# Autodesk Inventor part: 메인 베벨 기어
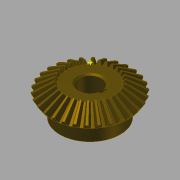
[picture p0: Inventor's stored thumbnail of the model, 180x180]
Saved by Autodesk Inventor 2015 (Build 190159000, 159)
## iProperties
Created: 2014-10
Part Number: 메인 베벨 기어
Material: 강철, 탄소
Document SubType Name: Modeling
Designer: KYOUNG IL JANG
Categories: <?xml version="1.0" encoding="UTF-16"?> <MemberInstance><Categories><FamilyTemplate><FamilyTemplateParameter ValueType="xs:double" Id="1" ObjectReferenceKey="da
Mass: 269.926 g
Surface Area: 108.837 cm^2
Volume: 34.2981 cm^3
Density: 7.87 g/cm^3
Appearance: 얼룩무늬
CustomPartVersion: 1
d48: 0.000 mm
d49: 0.000 mm
d50: 90.00 deg
d52: 0.000 mm
d53: 0.000 mm
d54: 0.00 deg
Author: SeoGD™ [www.esajin.kr]
Revision Number: 1
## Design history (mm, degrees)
node "맨 위 점"
node "메쉬 평면2"
sketch "톱니 본체 스케치"
  geometry: L1 (0, 0)-(28.669, -21.997); L2 (28.669, -21.997)-(31.109, -18.336); L3 (31.109, -18.336)-(0, 0); L4 (30, -20)-(0, 0); L5 (17.219, -13.212)-(18.685, -11.013); L6 (28.669, -21.997)-(17.219, -13.212); L7 (31.109, -18.336)-(18.685, -11.013); L8 (0, -39.387)-(0, 6.564) reference; L9 (0, -20)-(31.109, -20)
  constraints: 16 end point, 4 point on line, 3 perpendicular, 2 collinear, 1 horizontal alignment, 1 vertical alignment
  dimensions: "d0" = 60 diameter of L4.start L8 (= da_de); "d1" = 57.33744 diameter of L1.end L8 (= da_dfe); "d2" = 62.2188 diameter of L2.end L8 (= da_dae); "d3" = 14.4 distance between parallel lines of L2 L5 (= da_b); "d4" = 18.3359 vertical distance of L2.end L1.start (= da_ve)
revolve "톱니 본체" sketch "톱니 본체 스케치" stored, may be unused: angle "d5" = 90 deg
node "시작점"
node "톱니 평면"
sketch "시작 스케치"
  geometry: L1 (0, -23.505)-(0, 10.645) reference; L2 (-0.709, -2.928)-(0.709, -2.928); A1 r 19.188 centre (-19.457, -7.014) between (-0.709, -2.928) and (-3.232, 3.229); A2 r 19.188 centre (19.457, -7.014) between (3.232, 3.229) and (0.709, -2.928); A3 r 57.403 centre (0, -54.083) between (3.232, 3.229) and (-3.232, 3.229); 1 further point
  constraints: 6 point on circle, 3 centre point, 3 symmetric about line, 2 end point, 1 coincident, 1 perpendicular, 1 other
  dimensions: "d7" = 19.18795 radius of A1 (= fd_rr); "d8" = 19.45712 horizontal distance of point (0, -54.083) A1.centre (= fd_x); "d9" = 47.06905 vertical distance of point (0, -54.083) A1.centre (= fd_y); "d57" = 57.40327 radius of A3 (= 0.5 x fd_dva + 0.3 x da_he); "d58" = 51.15527 distance from line of A3.centre L2 (= 0.5 x fd_dva - 1.12 x da_he)
node "끝점"
  node "끝 평면"
sketch "3D 스케치 오른쪽"
  node "Helical Curve Right" dims "d65" = 229.90621 (computed from da_dm, da_delta, da_beta), "d66" = 31.5, "d67" = 60 (= da_de), "d68" = -9.82794 (= -da_delta), "d69" = 8.10972 (computed from fd_loft, da_delta)
node "끝 평면 오른쪽"
sketch "끝 스케치 오른쪽"
  geometry: L1 (0, -41.54)-(0, 13.178) reference; L2 (-0.422, -1.69)-(0.422, -1.69); A1 r 11.427 centre (-11.587, -4.123) between (-0.422, -1.69) and (-1.925, 1.977); A2 r 11.427 centre (11.587, -4.123) between (1.925, 1.977) and (0.422, -1.69); A3 r 34.184 centre (0, -32.153) between (1.925, 1.977) and (-1.925, 1.977); 1 further point
  constraints: 6 point on circle, 3 centre point, 3 symmetric about line, 2 end point, 1 coincident, 1 perpendicular, 1 other
  dimensions: "d70" = 11.58699 horizontal distance of A3.centre A1.centre (computed from fd_x, fd_ratio); "d71" = 28.03028 vertical distance of point (0, -32.153) A1.centre (computed from fd_y, fd_ratio); "d72" = 11.4267 radius of A1 (computed from fd_rr, fd_ratio); "d73" = 30.46369 distance from line of point (0, -32.153) L2 (computed from d58, fd_ratio); "d74" = 34.18446 radius of A3 (computed from d57, fd_ratio)
feature "로프트 오른쪽" sketch "끝 스케치 오른쪽" dims "d75" = 0, "d77" = 0, "d79" = 0, "d80" = 90 deg, "d85" = 20, "d92" = 90 deg, "d93" = 90 deg, "da_teethtype" = 0 [user parameter]
sketch "3D 스케치 왼쪽"
  node "Helical Curve Left" dims "d26" = 229.90621 (computed from da_dm, da_delta, da_beta), "d27" = 8.10972 (computed from fd_loft, da_delta), "d28" = 60 (= da_de), "d29" = -9.82794 (= -da_delta)
node "끝 평면 왼쪽"
sketch "끝 스케치 왼쪽" dims "d56" = 10.3728 (derived)
  geometry: L1 (0, -43.753)-(0, 15.405) reference; L2 (-0.422, -1.678)-(0.422, -1.678); A1 r 11.427 centre (-11.587, -4.111) between (-0.422, -1.678) and (-1.925, 1.988); A2 r 11.427 centre (11.587, -4.111) between (1.925, 1.988) and (0.422, -1.678); A3 r 34.184 centre (0, -32.142) between (1.925, 1.988) and (-1.925, 1.988); 2 further points; 1 other entity
  constraints: 6 point on circle, 3 centre point, 3 symmetric about line, 2 end point, 1 coincident, 2 other
  dimensions: "d30" = 11.4267 radius of A1 (computed from fd_rr, fd_ratio); "d31" = 11.58699 horizontal distance of point (0, -32.142) A1.centre (computed from fd_x, fd_ratio); "d32" = 28.03028 vertical distance of A1.centre point (0, -32.142) (computed from fd_y, fd_ratio); "d61" = 34.18446 radius of A3 (computed from d57, fd_ratio); "d62" = 30.46369 distance from line of point (0, -32.142) L2 (computed from d58, fd_ratio)
feature "로프트 왼쪽" sketch "끝 스케치 왼쪽" dims "d35" = 0, "d37" = 0, "d39" = 0, "d40" = 90 deg, "d84" = 10, "d90" = 90 deg, "d91" = 90 deg, "da_teethtype" = 0 [user parameter]
sketch "본체 스케치"
  geometry: L1 (0, -35.038)-(0, -19.531) reference; L2 (28.669, -21.997)-(17.219, -13.212) reference; L3 (17.219, -13.212)-(0, -13.212); L4 (28.669, -21.997)-(0, -21.997)
  constraints: 4 end point, 2 perpendicular, 2 point on line
revolve "본체 고정" sketch "본체 스케치" stored, may be unused: angle "d46" = 90 deg
feature "피치 지름" dims angle "d47" = 90 deg
sketch "스케치8"
  geometry: C1 r 22.5 at (0, 0); 1 further point
  constraints: 1 centre point, 1 coincident
  dimensions: "d94" = 45 diameter of C1
extrude "돌출1" join sketch "스케치8" distance "d95" = 13; taper "d96" = 0 deg
sketch "스케치9"
  geometry: 1 further point
hole "구멍1" sketch "스케치9" at (0, 0) diameter "d97" = 17; stored, may be unused: countersink angle "d101" = 90 deg, drill point angle "d103" = 118 deg; dims "d98" = 6, "d99" = 4, "d100" = 2, "d102" = 8
sketch "스케치10"
  geometry: L1 (8.124, 2.5)-(10.8, 2.5); L2 (10.8, 2.5)-(10.8, -2.5); L3 (10.8, -2.5)-(8.124, -2.5); A1 r 8.5 centre (0, 0) between (8.124, 2.5) and (8.124, -2.5) reference; 1 further point
  constraints: 6 end point, 2 parallel, 2 point on circle, 1 horizontal, 1 perpendicular
  dimensions: "d104" = 5 distance of L1.end L2.end; "d112" = 19.3 dimension on A1 L2
extrude "돌출2" cut sketch "스케치10" stored distance "d106" = 10; taper "d107" = 0 deg
chamfer "모따기1" distance "d108" = 1; stored, may be unused: second distance "d109" = 2, angle "d110" = 45 deg
fillet "모깎기1" dims "d111" = 2
body "Solid1"
feature "로프트" dims "d17" = 0, "d18" = 90 deg, "d19" = 0, "d20" = 90 deg, "d89" = 0, "da_teethtype" = 0 [user parameter]
pattern_circular "원형 패턴" dims angle "d22" = 360 deg, "d88" = 0, "da_teethtype" = 0 [user parameter]
pattern_circular "원형 패턴 오른쪽" dims angle "d82" = 360 deg, "da_teethtype" = 0 [user parameter]
pattern_circular "원형 패턴 왼쪽" dims angle "d42" = 360 deg, "da_teethtype" = 0 [user parameter]
sketch "끝 스케치"
  geometry: L1 (0, -15.359)-(0, 6.983) reference; L2 (-0.422, -1.69)-(0.422, -1.69); A1 r 11.427 centre (-11.587, -4.123) between (-0.422, -1.69) and (-1.925, 1.977); A2 r 11.427 centre (11.587, -4.123) between (1.925, 1.977) and (0.422, -1.69); A3 r 34.184 centre (0, -32.153) between (1.925, 1.977) and (-1.925, 1.977); 1 further point
  constraints: 6 point on circle, 3 centre point, 3 symmetric about line, 2 end point, 1 coincident, 1 other
  dimensions: "d12" = 11.4267 radius of A1 (computed from fd_rr, fd_ratio); "d15" = 11.58699 horizontal distance of A1.centre point (0, -32.153) (computed from fd_x, fd_ratio); "d16" = 28.03028 vertical distance of A1.centre point (0, -32.153) (computed from fd_y, fd_ratio); "d59" = 34.18446 radius of A3 (computed from d57, fd_ratio); "d60" = 30.46369 distance from line of A3.centre L2 (computed from d58, fd_ratio)
sketch "Sketch6"
  geometry: L1 (30, -20)-(0, 0) reference; L2 (0, -37.8)-(0, 6.3) reference
body "Srf1"
other parameters: "da_b" = 14.4 [user parameter; used in 2 equation terms], "da_de" = 60 [user parameter; used in 4 equation terms], "da_dae" = 62.2188 [user parameter; used in 2 equation terms], "da_dfe" = 57.33744 [user parameter; used in 1 equation term], "da_le" = 36.05551 [user parameter; used in 1 equation term], "da_omega" = 90 deg [user parameter; used in 1 equation term], "da_beta" = 0 [user parameter; used in 2 equation terms], "da_delta" = 9.82794 [user parameter; used in 8 equation terms], "da_alpha" = 20 deg [user parameter; used in 2 equation terms], "da_he" = 4.4 [user parameter; used in 4 equation terms], "da_ve" = 18.3359 [user parameter; used in 1 equation term], "fd_dv" = 108.16654 (computed from da_de, da_delta) [user parameter; used in 1 equation term], "fd_dva" = 112.16654 (computed from da_dae, da_delta) [user parameter; used in 3 equation terms], "fd_dvb" = 101.6433 (computed from fd_dv, da_alpha) [user parameter; used in 2 equation terms], "da_zv" = 540.83269 [user parameter; used in 1 equation term], "fd_loft" = 14.62 (= da_b + 0.05 x da_he) [user parameter; used in 4 equation terms], "fd_ratio" = 5.95514 (computed from da_le, fd_loft) [user parameter; used in 15 equation terms], "fd_rr" = 19.18795 (computed from fd_dd, fd_dvb) [user parameter; used in 6 equation terms], "fd_angle" = 0.29367 (computed from da_zv) [user parameter; used in 4 equation terms], "fd_x1" = 1.58802 (computed from da_dvw, fd_angle) [user parameter; used in 1 equation term], "fd_y1" = 54.05995 (computed from da_dvw, fd_angle) [user parameter; used in 1 equation term], "fd_x2" = 17.8691 (computed from fd_rr, fd_angle2, fd_angle) [user parameter; used in 1 equation term], "fd_y2" = 6.9909 (computed from fd_rr, fd_angle2, fd_angle) [user parameter; used in 1 equation term], "fd_x" = 19.45712 (= fd_x1 + fd_x2) [user parameter; used in 4 equation terms], "fd_y" = 47.06905 (= fd_y1 - fd_y2) [user parameter; used in 4 equation terms], "fd_angle2" = 3.43555 (computed from fd_dvb, fd_dd, da_alpha) [user parameter; used in 2 equation terms], "fd_dd" = 108.64654 (= fd_dva - 0.8 x da_he) [user parameter; used in 2 equation terms], "da_dvw" = 108.16654 [user parameter; used in 2 equation terms], "d11" = 14.62 (= fd_loft), "da_dm" = 48.01848 [user parameter; used in 2 equation terms], "da_x" = 0 [user parameter], "da_m" = 2 [user parameter], "d48" = 0, "d49" = 0, "d50" = 90 deg (= da_omega), "d51" = 6 deg (computed from da_z), "d52" = 0, "d53" = 0, "d54" = 0 deg
